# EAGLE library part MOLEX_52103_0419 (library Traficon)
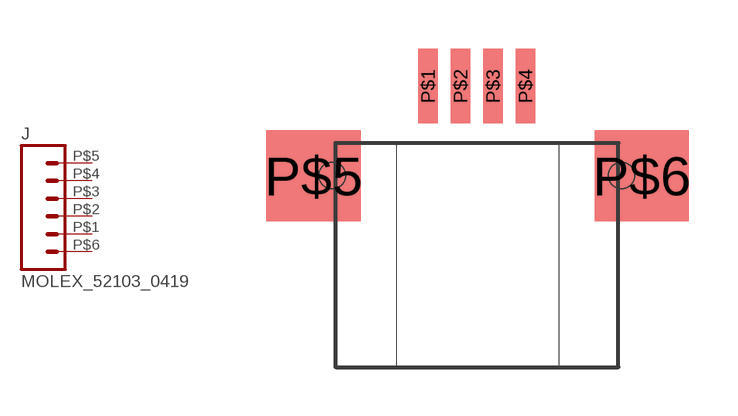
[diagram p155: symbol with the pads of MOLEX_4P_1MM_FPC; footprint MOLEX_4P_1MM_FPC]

Designator prefix J

## MOLEX_52103_0419  [MOLEX_4P_1MM_FPC]
P$1  1
P$2  2
P$3  3
P$4  4
P$5  P$1  pas
P$6  P$2  pas

## Footprint MOLEX_4P_1MM_FPC (pad centres in mm)
smd 0.6 x 2.3: P$1 -1.519,4.359; P$2 -0.519,4.359; P$3 0.481,4.359; P$4 1.481,4.359
smd 2.9 x 2.8: P$5 -5.05,1.6; P$6 5.05,1.6
hole 0.8 at -4.469,1.609
hole 0.8 at 4.431,1.609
